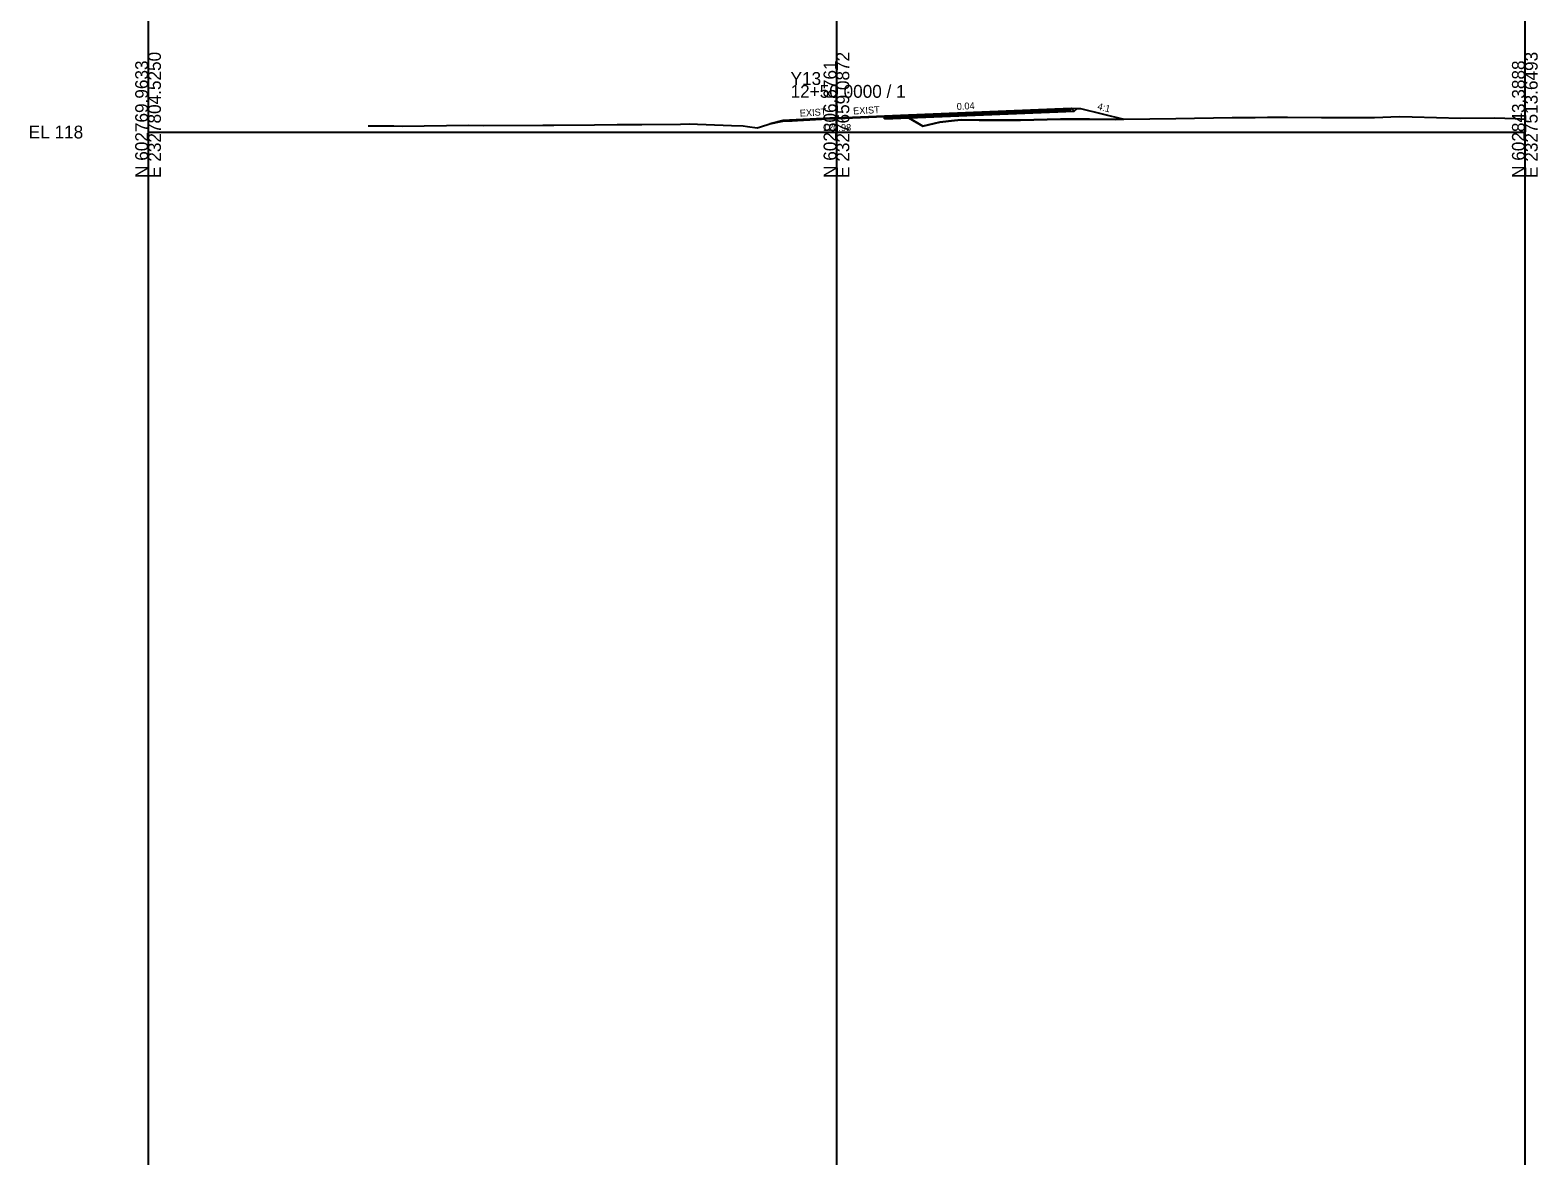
# Model space of a CAD drawing. Extents: x -26 to 1603, y -711 to 1241.
# Drawn here: x -25.7 to 302.8, y -223.2 to 22.2 of the extents above; entities that cross this region are included whole.
import ezdxf

# ---------------------------------------------------------------- set-up
doc = ezdxf.new("R2010")
doc.units = 0
for name, color, linetype in [('Exist CMT Pavement', 7, 'Continuous'), ('Exist Cross Section Cell', 7, 'Continuous'), ('Exist XS Center Line Elevation Label', 7, 'Continuous'), ('Exist XS Ground Line', 7, 'Continuous'), ('Prop CMT Pvmt Course 1', 7, 'Continuous'), ('Prop CMT Pvmt Course 1 Wedge', 7, 'Continuous'), ('Prop CMT Pvmt Course 2', 7, 'Continuous'), ('Prop CMT Pvmt Course 3', 7, 'Continuous'), ('Prop CMT Pvmt Surface', 7, 'Continuous'), ('Prop CMT Pvmt Surface Shoulder', 7, 'Continuous'), ('Prop CMT Pvmt Wedge Surface 1', 7, 'Continuous'), ('Prop CMT Pvmt Wedge Surface 2', 7, 'Continuous'), ('Prop CMT Pvmt Wedge Surface 3', 7, 'Continuous'), ('Prop CMT Shld Paved Course 1', 7, 'Continuous'), ('Prop CMT Shld Paved Course 2', 7, 'Continuous'), ('Prop CMT Shld Paved Course 3', 7, 'Continuous'), ('Prop CMT Slope Grass', 7, 'Continuous'), ('Prop CMT Subgrade Earthwork', 7, 'Continuous'), ('Prop XS Earthwork Shape', 7, 'Continuous'), ('Prop XS SE Text', 7, 'Continuous'), ('Prop XS Side Slope Text', 7, 'Continuous'), ('Scratch_Level_0', 7, 'Continuous'), ('Scratch_Level_1', 7, 'Continuous'), ('Scratch_Level_9', 7, 'Continuous')]:
    doc.layers.add(name, color=color, linetype=linetype)

msp = doc.modelspace()

# ---------------------------------------------------------------- linework, layer by layer
at = {"layer": 'Exist CMT Pavement'}
msp.add_lwpolyline([(138.33, 2.34), (139.14, 2.41), (140.33, 2.48), (141.54, 2.55), (144.23, 2.7), (146.72, 2.83), (147.78, 2.88), (149.31, 2.95), (149.89, 2.98), (151.42, 3.03), (151.9, 3.05), (153.42, 3.12), (154.49, 3.17), (156.3, 3.24), (157.08, 3.28), (158.34, 3.32), (159.67, 3.37), (160.49, 3.41)], dxfattribs=at)
at = {"layer": 'Exist Cross Section Cell'}
for p, q in [((150, 0), (150, 10.27)), ((0, 0), (150, 0)), ((150, 0), (300, 0))]:
    msp.add_line(p, q, dxfattribs=at)
at = {"layer": 'Exist XS Ground Line'}
msp.add_lwpolyline([(47.95, 1.38), (48.57, 1.33), (53.54, 1.32), (55.35, 1.3), (69.83, 1.48), (73.04, 1.43), (86.05, 1.49), (86.93, 1.52), (88.42, 1.51), (97.25, 1.57), (102.21, 1.62), (107.56, 1.64), (116.01, 1.73), (117.88, 1.77), (127.15, 1.46), (129.66, 1.34), (130.65, 1.23), (132.73, 0.91), (133.42, 1.15), (135.49, 1.78), (138.33, 2.34), (139.14, 2.41), (140.33, 2.48), (141.54, 2.55), (144.23, 2.7), (146.72, 2.83), (147.78, 2.88), (149.31, 2.95), (149.89, 2.98), (151.42, 3.03), (151.9, 3.05), (153.42, 3.12), (154.49, 3.17), (156.3, 3.24), (157.08, 3.28), (158.34, 3.32), (159.67, 3.37), (160.49, 3.41), (161.28, 3.42), (162.36, 3.35), (165.72, 3.11), (168.81, 1.26), (172.51, 2.17), (175.75, 2.5), (177.18, 2.69), (181.11, 2.61), (190.08, 2.59), (198.8, 2.78), (200.4, 2.82), (205.14, 2.8), (210.71, 2.77), (212.6, 2.78), (223.92, 2.97), (236.23, 3.18), (237.09, 3.18), (238.4, 3.19), (241.22, 3.16), (243.9, 3.21), (247.02, 3.23), (248.29, 3.24), (255.73, 3.17), (260.29, 3.17), (267.24, 3.19), (272.6, 3.36), (275.48, 3.31), (286.09, 3.04), (293.38, 3.12), (297.87, 2.94), (300, 2.8)], dxfattribs=at)
at = {"layer": 'Prop CMT Pvmt Course 1'}
for points in [[(150, 3.11), (160.49, 3.53)], [(160.49, 3.41), (150.01, 2.98)], [(160.49, 3.41), (160.49, 3.53)], [(160.49, 3.53), (160.49, 3.41)], [(150, 3.11), (138.33, 2.49)]]:
    msp.add_lwpolyline(points, dxfattribs=at)
at = {"layer": 'Prop CMT Pvmt Course 1 Wedge'}
msp.add_lwpolyline([(150.01, 2.98), (160.49, 3.41)], dxfattribs=at)
at = {"layer": 'Prop CMT Pvmt Course 2'}
for points in [[(160.49, 3.41), (160.49, 3.41)], [(160.49, 3.28), (160.49, 3.28)]]:
    msp.add_lwpolyline(points, dxfattribs=at)
at = {"layer": 'Prop CMT Pvmt Course 3'}
msp.add_lwpolyline([(160.49, 3.28), (160.49, 2.86)], dxfattribs=at)
at = {"layer": 'Prop CMT Pvmt Surface'}
for points in [[(150, 3.11), (160.49, 3.53)], [(150, 3.11), (138.33, 2.49)]]:
    msp.add_lwpolyline(points, dxfattribs=at)
at = {"layer": 'Prop CMT Pvmt Surface Shoulder'}
msp.add_lwpolyline([(160.49, 3.53), (201.17, 5.18)], dxfattribs=at)
at = {"layer": 'Prop CMT Pvmt Wedge Surface 1'}
for points in [[(150.01, 2.98), (160.49, 3.41)], [(160.49, 3.53), (160.49, 3.41)], [(160.49, 3.28), (160.49, 3.53)]]:
    msp.add_lwpolyline(points, dxfattribs=at)
at = {"layer": 'Prop CMT Pvmt Wedge Surface 2'}
msp.add_lwpolyline([(160.49, 3.28), (160.49, 3.53)], dxfattribs=at)
at = {"layer": 'Prop CMT Pvmt Wedge Surface 3'}
msp.add_lwpolyline([(160.49, 3.28), (160.49, 3.53)], dxfattribs=at)
at = {"layer": 'Prop CMT Shld Paved Course 1'}
for points in [[(201.17, 4.93), (160.49, 3.28)], [(160.49, 3.28), (160.49, 3.53)], [(163.93, 3.67), (201.17, 5.18), (201.81, 4.54)]]:
    msp.add_lwpolyline(points, dxfattribs=at)
at = {"layer": 'Prop CMT Shld Paved Course 2'}
for points in [[(160.49, 3.28), (201.17, 4.93)], [(201.17, 4.93), (160.49, 3.28)], [(201.41, 4.94), (201.41, 4.94)], [(160.49, 3.28), (160.49, 3.28)]]:
    msp.add_lwpolyline(points, dxfattribs=at)
at = {"layer": 'Prop CMT Shld Paved Course 3'}
for points in [[(160.49, 3.28), (201.17, 4.93)], [(201.17, 4.51), (160.49, 2.86)], [(201.41, 4.94), (201.41, 4.94)], [(201.41, 4.94), (201.81, 4.54)], [(160.49, 2.86), (160.49, 3.28)]]:
    msp.add_lwpolyline(points, dxfattribs=at)
at = {"layer": 'Prop CMT Slope Grass'}
for p, q in [((201.17, 5.18), (203.17, 5.14)), ((203.17, 5.14), (212.62, 2.78)), ((138.33, 2.49), (135.49, 1.78))]:
    msp.add_line(p, q, dxfattribs=at)
at = {"layer": 'Prop CMT Subgrade Earthwork'}
for p, q in [((160.49, 2.86), (160.49, 3.41)), ((135.49, 1.78), (138.33, 2.34))]:
    msp.add_line(p, q, dxfattribs=at)
for points in [[(160.49, 2.86), (201.81, 4.54)], [(201.81, 4.54), (202.43, 5.16)]]:
    msp.add_lwpolyline(points, dxfattribs=at)
at = {"layer": 'Prop XS Earthwork Shape'}
for points in [[(160.49, 2.86), (160.49, 3.41), (161.28, 3.42), (162.36, 3.35), (165.72, 3.11), (165.78, 3.08)], [(203.17, 5.14), (212.62, 2.78), (212.6, 2.78), (210.71, 2.77), (205.14, 2.8), (200.4, 2.82), (198.8, 2.78), (190.08, 2.59), (181.11, 2.61), (177.18, 2.69), (175.75, 2.5), (172.51, 2.17), (168.81, 1.26), (165.78, 3.08), (201.81, 4.54), (202.43, 5.16)]]:
    msp.add_lwpolyline(points, close=True, dxfattribs=at)
at = {"layer": 'Scratch_Level_1'}
msp.add_line((150, 3.11), (160.49, 3.53), dxfattribs=at)
at = {"layer": 'Scratch_Level_9'}
for p, q in [((0, 1241.32), (0, -711.39)), ((150, 1241.32), (150, -711.39)), ((300, 1241.32), (300, -711.39))]:
    msp.add_line(p, q, dxfattribs=at)

# ---------------------------------------------------------------- texts
at = {"layer": 'Exist Cross Section Cell'}
for s, p in [('E 2327804.5250', (2.8, -10)), ('E 2327659.0872', (152.8, -10)), ('E 2327513.6493', (302.8, -10)), ('N 602769.9633', (0, -10)), ('N 602806.6761', (150, -10)), ('N 602843.3888', (300, -10))]:
    msp.add_text(s, height=2.8, rotation=90, dxfattribs=at).set_placement(p)
for s, p in [('Y13', (140, 10.27)), ('12+50.0000 / 1', (140, 7.47)), ('EL 118', (-26, -1.4))]:
    msp.add_text(s, height=2.8, dxfattribs=at).set_placement(p)
at = {"layer": 'Exist XS Center Line Elevation Label'}
msp.add_text('120.98', height=1.5, dxfattribs=at).set_placement((147.08, 0.23))
at = {"layer": 'Prop XS SE Text'}
for s, p in [('EXIST', (142.05, 3.37)), ('EXIST', (153.67, 3.84)), ('0.04', (176.25, 4.81))]:
    msp.add_text(s, height=1.5, rotation=3.0314, dxfattribs=at).set_placement(p)
at = {"layer": 'Prop XS Side Slope Text'}
msp.add_text('4:1', height=1.5, rotation=345.9638, dxfattribs=at).set_placement((206.77, 4.95))
at = {"layer": 'Scratch_Level_0'}
for s, p in [('RT_PV1_OEEOP', (160.39, 3.52)), ('RT_PV3_OEEOP', (160.39, 3.4)), ('RT_PV1_OEOT', (160.4, 3.52)), ('RT_PV3_OEOT', (160.39, 3.27)), ('RT_PV2_OEOT', (160.39, 3.27)), ('RT_PS1_OEOP', (201.1, 5.19)), ('RT_PS3_Shelf_Out', (201.27, 4.93)), ('RT_PS3_OEOP', (201.31, 4.93)), ('RT_PS2_OEOP', (201.31, 4.93)), ('RT_Sub_Trench_Out', (201.66, 4.53)), ('RT_Sub_Trench_Out_DLT', (202.22, 5.13)), ('LT_PV1_OEEOP', (139.04, 2.4)), ('RT_Sub_OEOT', (160.39, 2.85))]:
    msp.add_text(s, height=0.02, dxfattribs=at).set_placement(p)

doc.saveas('drawing.dxf')
